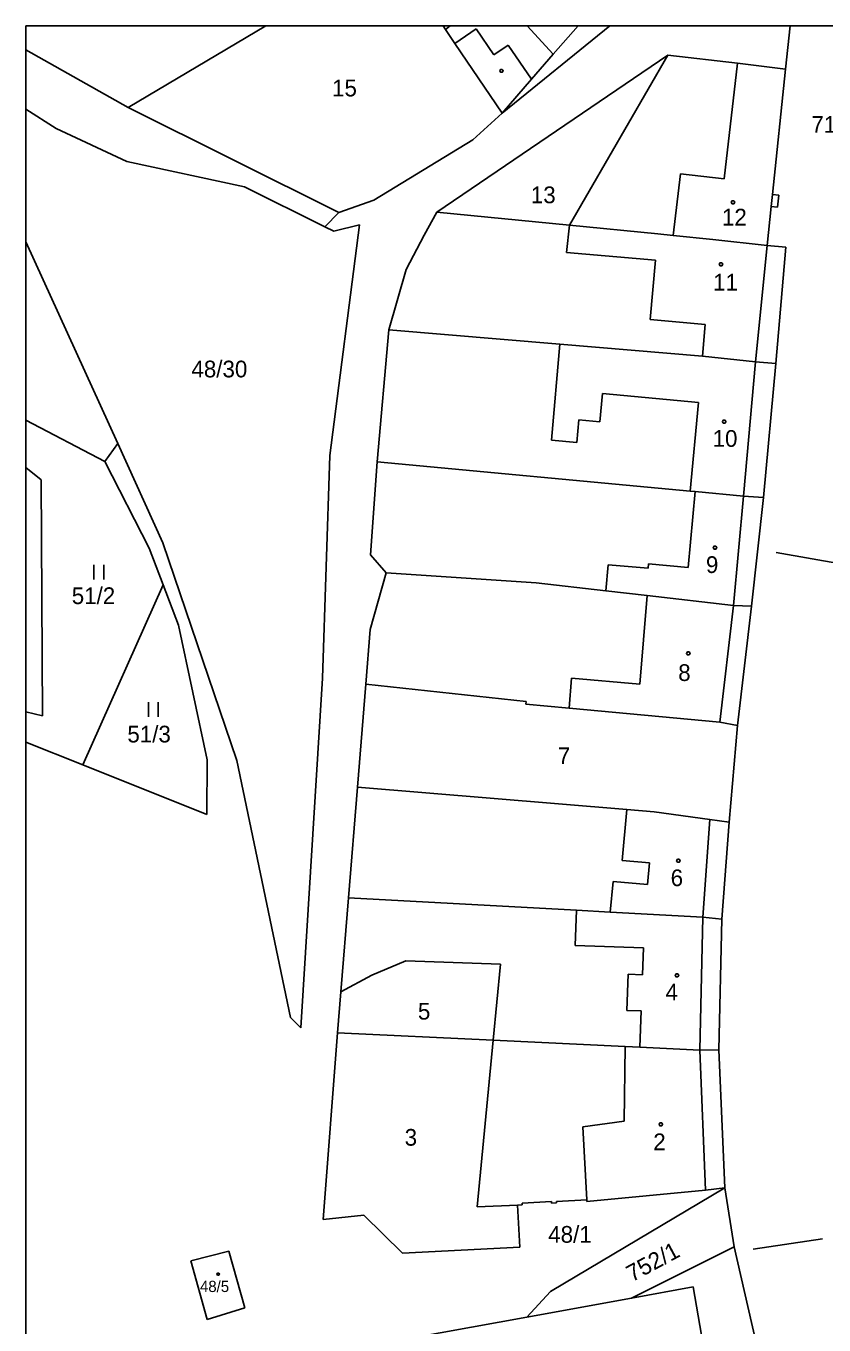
# Model space of a CAD drawing. Extents: x -639590 to -639298, y -1193269 to -1192863.
# Drawn here: x -639590.4 to -639509.2, y -1192995.4 to -1192863.3 of the extents above; entities that cross this region are included whole.
import ezdxf

# ---------------------------------------------------------------- set-up
doc = ezdxf.new("R2010")
doc.units = 0
for name, color, linetype in [('Vrstva 1', 7, 'Continuous'), ('Vrstva 2', 7, 'Continuous'), ('Vrstva 25', 7, 'Continuous'), ('Vrstva 3', 7, 'Continuous'), ('Vrstva 4', 7, 'Continuous'), ('Vrstva 5', 7, 'Continuous'), ('Vrstva 61', 7, 'Continuous')]:
    doc.layers.add(name, color=color, linetype=linetype)

msp = doc.modelspace()

# ---------------------------------------------------------------- linework, layer by layer
at = {"layer": 'Vrstva 1'}
for p, q in [((-639565.97, -1192863.27), (-639580, -1192871.57)), ((-639547.69, -1192863.63), (-639547.93, -1192863.27)), ((-639546.73, -1192865.04), (-639547.69, -1192863.63)), ((-639530.97, -1192863.27), (-639541.93, -1192872.12)), ((-639534.19, -1192863.27), (-639536.75, -1192866.15)), ((-639512.63, -1192863.27), (-639513.1, -1192867.65)), ((-639541.93, -1192872.12), (-639546.73, -1192865.04)), ((-639580, -1192871.57), (-639590.39, -1192865.7)), ((-639525.06, -1192866.23), (-639548.56, -1192882.19)), ((-639536.75, -1192866.15), (-639538.95, -1192868.69)), ((-639525.06, -1192866.23), (-639535.07, -1192883.53)), ((-639517.99, -1192867.05), (-639525.06, -1192866.23)), ((-639513.1, -1192867.65), (-639517.99, -1192867.05)), ((-639514.43, -1192880.41), (-639513.1, -1192867.65)), ((-639538.95, -1192868.69), (-639541.93, -1192872.12)), ((-639590.39, -1192871.73), (-639587.31, -1192873.7)), ((-639580, -1192871.57), (-639558.56, -1192882.23)), ((-639541.93, -1192872.12), (-639544.9, -1192874.86)), ((-639587.31, -1192873.7), (-639580.13, -1192877.06)), ((-639544.9, -1192874.86), (-639555, -1192880.97)), ((-639580.13, -1192877.06), (-639568.16, -1192879.64)), ((-639568.16, -1192879.64), (-639559.97, -1192883.7)), ((-639558.56, -1192882.23), (-639555, -1192880.97)), ((-639513.76, -1192880.48), (-639514.43, -1192880.41)), ((-639513.89, -1192881.71), (-639513.76, -1192880.48)), ((-639559.97, -1192883.7), (-639558.56, -1192882.23)), ((-639548.56, -1192882.19), (-639549.88, -1192884.53)), ((-639535.07, -1192883.53), (-639548.56, -1192882.19)), ((-639514.97, -1192885.59), (-639514.56, -1192881.64)), ((-639514.56, -1192881.64), (-639513.89, -1192881.71)), ((-639559.97, -1192883.7), (-639559.07, -1192884.15)), ((-639556.45, -1192883.48), (-639559.45, -1192906.94)), ((-639559.07, -1192884.15), (-639556.45, -1192883.48)), ((-639526.07, -1192884.42), (-639535.07, -1192883.53)), ((-639581.05, -1192905.73), (-639590.39, -1192885.22)), ((-639551.68, -1192888.03), (-639549.88, -1192884.53)), ((-639524.51, -1192884.57), (-639526.07, -1192884.42)), ((-639520.5, -1192884.97), (-639524.51, -1192884.57)), ((-639514.97, -1192885.59), (-639520.5, -1192884.97)), ((-639513.07, -1192885.76), (-639514.97, -1192885.59)), ((-639514.06, -1192897.59), (-639513.07, -1192885.76)), ((-639553.46, -1192894.18), (-639551.68, -1192888.03)), ((-639553.46, -1192894.18), (-639554.66, -1192907.58)), ((-639536.07, -1192895.63), (-639553.46, -1192894.18)), ((-639521.55, -1192896.85), (-639536.07, -1192895.63)), ((-639516.13, -1192897.41), (-639521.55, -1192896.85)), ((-639514.06, -1192897.59), (-639516.13, -1192897.41)), ((-639515.33, -1192911.2), (-639514.06, -1192897.59)), ((-639590.39, -1192903.36), (-639582.38, -1192907.56)), ((-639581.05, -1192905.73), (-639582.38, -1192907.56)), ((-639576.45, -1192915.83), (-639581.05, -1192905.73)), ((-639582.38, -1192907.56), (-639577.84, -1192916.35)), ((-639559.45, -1192906.94), (-639560.22, -1192929.6)), ((-639555.33, -1192917.06), (-639554.66, -1192907.58)), ((-639522.8, -1192910.56), (-639554.66, -1192907.58)), ((-639590.39, -1192908.18), (-639588.84, -1192909.43)), ((-639588.7, -1192933.43), (-639588.84, -1192909.43)), ((-639522.3, -1192910.61), (-639522.8, -1192910.56)), ((-639517.37, -1192911.07), (-639522.3, -1192910.61)), ((-639515.33, -1192911.2), (-639517.37, -1192911.07)), ((-639516.56, -1192922.27), (-639515.33, -1192911.2)), ((-639568.92, -1192937.95), (-639576.45, -1192915.83)), ((-639577.84, -1192916.35), (-639576.43, -1192920.08)), ((-639553.74, -1192918.86), (-639555.33, -1192917.06)), ((-639553.74, -1192918.86), (-639555.36, -1192924.62)), ((-639538.45, -1192919.9), (-639553.74, -1192918.86)), ((-639576.43, -1192920.08), (-639584.61, -1192938.41)), ((-639576.43, -1192920.08), (-639574.87, -1192924.21)), ((-639531.39, -1192920.71), (-639538.45, -1192919.9)), ((-639527.16, -1192921.19), (-639531.39, -1192920.71)), ((-639518.37, -1192922.19), (-639527.16, -1192921.19)), ((-639516.56, -1192922.27), (-639518.37, -1192922.19)), ((-639517.98, -1192934.38), (-639516.56, -1192922.27)), ((-639574.87, -1192924.21), (-639571.95, -1192937.9)), ((-639555.36, -1192924.62), (-639555.81, -1192930.2)), ((-639560.22, -1192929.6), (-639562.4, -1192965.13)), ((-639556.66, -1192940.65), (-639555.81, -1192930.2)), ((-639539.5, -1192931.94), (-639555.81, -1192930.2)), ((-639590.39, -1192933.02), (-639588.7, -1192933.43)), ((-639539.5, -1192931.94), (-639539.53, -1192932.24)), ((-639535.12, -1192932.64), (-639539.53, -1192932.24)), ((-639519.77, -1192934.05), (-639535.12, -1192932.64)), ((-639517.98, -1192934.38), (-639519.77, -1192934.05)), ((-639518.83, -1192944.22), (-639517.98, -1192934.38)), ((-639590.39, -1192936.1), (-639584.61, -1192938.41)), ((-639571.98, -1192943.45), (-639571.95, -1192937.9)), ((-639563.48, -1192964.08), (-639568.92, -1192937.95)), ((-639584.61, -1192938.41), (-639571.98, -1192943.45)), ((-639557.57, -1192951.91), (-639556.66, -1192940.65)), ((-639529.25, -1192942.94), (-639556.66, -1192940.65)), ((-639526.45, -1192943.17), (-639529.25, -1192942.94)), ((-639520.79, -1192943.95), (-639526.45, -1192943.17)), ((-639518.83, -1192944.22), (-639520.79, -1192943.95)), ((-639519.57, -1192954.08), (-639518.83, -1192944.22)), ((-639558.35, -1192961.49), (-639557.57, -1192951.91)), ((-639534.37, -1192953.17), (-639557.57, -1192951.91)), ((-639530.93, -1192953.36), (-639534.37, -1192953.17)), ((-639521.49, -1192953.87), (-639530.93, -1192953.36)), ((-639519.57, -1192954.08), (-639521.49, -1192953.87)), ((-639519.87, -1192967.38), (-639519.57, -1192954.08)), ((-639555.2, -1192959.79), (-639551.74, -1192958.33)), ((-639542.1, -1192958.67), (-639551.74, -1192958.33)), ((-639542.83, -1192966.4), (-639542.1, -1192958.67)), ((-639558.35, -1192961.49), (-639555.2, -1192959.79)), ((-639558.69, -1192965.64), (-639558.35, -1192961.49)), ((-639562.4, -1192965.13), (-639563.48, -1192964.08)), ((-639558.69, -1192965.64), (-639560.13, -1192984.63)), ((-639542.83, -1192966.4), (-639558.69, -1192965.64)), ((-639542.83, -1192966.4), (-639544.48, -1192983.34)), ((-639529.4, -1192967.04), (-639542.83, -1192966.4)), ((-639527.9, -1192967.11), (-639529.4, -1192967.04)), ((-639521.81, -1192967.4), (-639527.9, -1192967.11)), ((-639519.87, -1192967.38), (-639521.81, -1192967.4)), ((-639519.26, -1192981.41), (-639519.87, -1192967.38)), ((-639519.26, -1192981.41), (-639537.01, -1192991.95)), ((-639521.22, -1192981.65), (-639533.3, -1192982.79)), ((-639521.22, -1192981.65), (-639519.26, -1192981.41)), ((-639519.26, -1192981.41), (-639518.33, -1192987.4)), ((-639544.48, -1192983.34), (-639540.36, -1192983.16)), ((-639540.36, -1192983.16), (-639539.89, -1192983.14)), ((-639540.12, -1192987.45), (-639540.36, -1192983.16)), ((-639539.9, -1192982.97), (-639536.91, -1192982.81)), ((-639539.89, -1192983.14), (-639539.9, -1192982.97)), ((-639536.91, -1192982.81), (-639536.9, -1192982.97)), ((-639536.9, -1192982.97), (-639536.4, -1192982.94)), ((-639533.31, -1192982.61), (-639536.41, -1192982.78)), ((-639536.4, -1192982.94), (-639536.41, -1192982.78)), ((-639533.3, -1192982.79), (-639533.31, -1192982.61)), ((-639560.13, -1192984.63), (-639555.99, -1192984.2)), ((-639555.99, -1192984.2), (-639552.08, -1192988.04)), ((-639573.61, -1192988.84), (-639569.73, -1192987.84)), ((-639569.73, -1192987.84), (-639568.13, -1192993.61)), ((-639540.12, -1192987.45), (-639552.08, -1192988.04)), ((-639518.33, -1192987.4), (-639528.76, -1192992.62)), ((-639518.33, -1192987.4), (-639513.38, -1193008.98)), ((-639571.96, -1192994.78), (-639573.61, -1192988.84)), ((-639537.01, -1192991.95), (-639539.42, -1192994.56)), ((-639528.76, -1192992.62), (-639522.49, -1192991.48)), ((-639521.26, -1192998.64), (-639522.49, -1192991.48)), ((-639568.13, -1192993.61), (-639571.96, -1192994.78)), ((-639539.42, -1192994.56), (-639528.76, -1192992.62)), ((-639553.86, -1192997.18), (-639539.42, -1192994.56))]:
    msp.add_line(p, q, dxfattribs=at)
at = {"layer": 'Vrstva 25'}
for p, q in [((-639514.03, -1192916.81), (-639507.28, -1192917.98)), ((-639516.39, -1192987.64), (-639509.32, -1192986.58))]:
    msp.add_line(p, q, dxfattribs=at)
at = {"layer": 'Vrstva 3'}
for p, q in [((-639583.48, -1192918.05), (-639583.48, -1192919.55)), ((-639582.48, -1192919.55), (-639582.48, -1192918.05)), ((-639577.93, -1192932.02), (-639577.93, -1192933.52)), ((-639576.93, -1192933.52), (-639576.93, -1192932.02))]:
    msp.add_line(p, q, dxfattribs=at)
at = {"layer": 'Vrstva 4'}
for p, q in [((-639547.69, -1192863.63), (-639547.22, -1192863.27)), ((-639544.56, -1192863.57), (-639546.73, -1192865.04)), ((-639542.78, -1192866.2), (-639544.56, -1192863.57)), ((-639536.75, -1192866.15), (-639539.37, -1192863.27)), ((-639541.32, -1192865.21), (-639542.78, -1192866.2)), ((-639538.95, -1192868.69), (-639541.32, -1192865.21)), ((-639517.99, -1192867.05), (-639519.35, -1192878.82)), ((-639524.51, -1192884.57), (-639523.78, -1192878.31)), ((-639523.78, -1192878.31), (-639519.35, -1192878.82)), ((-639514.56, -1192881.64), (-639514.43, -1192880.41)), ((-639535.07, -1192883.53), (-639535.39, -1192886.3)), ((-639535.39, -1192886.3), (-639526.32, -1192887.09)), ((-639514.97, -1192885.59), (-639516.13, -1192897.41)), ((-639526.32, -1192887.09), (-639526.87, -1192893.1)), ((-639526.87, -1192893.1), (-639521.26, -1192893.61)), ((-639521.26, -1192893.61), (-639521.55, -1192896.85)), ((-639536.07, -1192895.63), (-639536.92, -1192905.37)), ((-639516.13, -1192897.41), (-639517.37, -1192911.07)), ((-639531.98, -1192903.52), (-639531.71, -1192900.63)), ((-639531.71, -1192900.63), (-639521.95, -1192901.55)), ((-639521.95, -1192901.55), (-639522.8, -1192910.56)), ((-639534.33, -1192905.61), (-639534.12, -1192903.32)), ((-639534.12, -1192903.32), (-639531.98, -1192903.52)), ((-639536.92, -1192905.37), (-639534.33, -1192905.61)), ((-639522.3, -1192910.61), (-639522.99, -1192918.33)), ((-639517.37, -1192911.07), (-639518.37, -1192922.19)), ((-639531.39, -1192920.71), (-639531.15, -1192918.05)), ((-639531.15, -1192918.05), (-639527.06, -1192918.41)), ((-639527.06, -1192918.41), (-639527.02, -1192917.96)), ((-639527.02, -1192917.96), (-639522.99, -1192918.33)), ((-639527.16, -1192921.19), (-639527.92, -1192930.18)), ((-639518.37, -1192922.19), (-639519.77, -1192934.05)), ((-639535.12, -1192932.64), (-639534.86, -1192929.59)), ((-639534.86, -1192929.59), (-639527.92, -1192930.18)), ((-639529.25, -1192942.94), (-639529.72, -1192948.11)), ((-639520.79, -1192943.95), (-639521.49, -1192953.87)), ((-639529.72, -1192948.11), (-639526.93, -1192948.37)), ((-639527.13, -1192950.57), (-639526.93, -1192948.37)), ((-639530.93, -1192953.36), (-639530.64, -1192950.25)), ((-639530.64, -1192950.25), (-639527.13, -1192950.57)), ((-639534.37, -1192953.17), (-639534.5, -1192956.77)), ((-639521.49, -1192953.87), (-639521.81, -1192967.4)), ((-639527.54, -1192957.02), (-639534.5, -1192956.77)), ((-639527.54, -1192957.02), (-639527.64, -1192959.74)), ((-639529.1, -1192959.69), (-639529.23, -1192963.36)), ((-639527.64, -1192959.74), (-639529.1, -1192959.69)), ((-639529.23, -1192963.36), (-639527.77, -1192963.41)), ((-639527.77, -1192963.41), (-639527.9, -1192967.11)), ((-639529.4, -1192967.04), (-639529.52, -1192974.62)), ((-639521.81, -1192967.4), (-639521.22, -1192981.65)), ((-639529.52, -1192974.62), (-639533.72, -1192975.2)), ((-639533.72, -1192975.2), (-639533.31, -1192982.61))]:
    msp.add_line(p, q, dxfattribs=at)
at = {"layer": 'Vrstva 5'}
for points in [[(-639541.91, -1192867.68), (-639541.82, -1192867.83), (-639541.91, -1192867.98), (-639542.09, -1192867.98), (-639542.18, -1192867.83), (-639542.09, -1192867.68)], [(-639518.35, -1192881.04), (-639518.26, -1192881.19), (-639518.35, -1192881.34), (-639518.53, -1192881.34), (-639518.62, -1192881.19), (-639518.53, -1192881.04)], [(-639519.57, -1192887.35), (-639519.48, -1192887.5), (-639519.57, -1192887.65), (-639519.75, -1192887.65), (-639519.84, -1192887.5), (-639519.75, -1192887.35)], [(-639519.24, -1192903.34), (-639519.15, -1192903.49), (-639519.24, -1192903.64), (-639519.42, -1192903.64), (-639519.51, -1192903.49), (-639519.42, -1192903.34)], [(-639520.18, -1192916.16), (-639520.09, -1192916.31), (-639520.18, -1192916.46), (-639520.36, -1192916.46), (-639520.45, -1192916.31), (-639520.36, -1192916.16)], [(-639522.9, -1192926.92), (-639522.81, -1192927.07), (-639522.9, -1192927.22), (-639523.08, -1192927.22), (-639523.17, -1192927.07), (-639523.08, -1192926.92)], [(-639523.9, -1192948), (-639523.81, -1192948.15), (-639523.9, -1192948.3), (-639524.08, -1192948.3), (-639524.17, -1192948.15), (-639524.08, -1192948)], [(-639524.05, -1192959.66), (-639523.96, -1192959.81), (-639524.05, -1192959.96), (-639524.23, -1192959.96), (-639524.32, -1192959.81), (-639524.23, -1192959.66)], [(-639525.69, -1192974.81), (-639525.6, -1192974.96), (-639525.69, -1192975.11), (-639525.87, -1192975.11), (-639525.96, -1192974.96), (-639525.87, -1192974.81)], [(-639570.77, -1192990.08), (-639570.71, -1192990.18), (-639570.77, -1192990.28), (-639570.89, -1192990.28), (-639570.95, -1192990.18), (-639570.89, -1192990.08)]]:
    msp.add_lwpolyline(points, close=True, dxfattribs=at)
at = {"layer": 'Vrstva 61'}
for points in [[(-639590.39, -1193268.77), (-639590.39, -1192863.27)], [(-639590.39, -1192863.27), (-639298.39, -1192863.27)]]:
    msp.add_lwpolyline(points, dxfattribs=at)

# ---------------------------------------------------------------- texts
at = {"layer": 'Vrstva 2'}
for s, height, p in [('15', 1.7, (-639559.24, -1192870.43)), ('715/1', 1.7, (-639510.46, -1192874.13)), ('13', 1.7, (-639539.01, -1192881.29)), ('12', 1.7, (-639519.56, -1192883.56)), ('11', 1.7, (-639520.46, -1192890.17)), ('48/30', 1.7, (-639573.55, -1192899)), ('10', 1.7, (-639520.51, -1192906.06)), ('9', 1.7, (-639521.19, -1192918.89)), ('51/2', 1.7, (-639585.73, -1192922.05)), ('8', 1.7, (-639524.01, -1192929.87)), ('51/3', 1.7, (-639580.07, -1192936.12)), ('7', 1.7, (-639536.26, -1192938.32)), ('6', 1.7, (-639524.78, -1192950.73)), ('4', 1.7, (-639525.3, -1192962.35)), ('5', 1.7, (-639550.5, -1192964.3)), ('3', 1.7, (-639551.85, -1192977.12)), ('2', 1.7, (-639526.55, -1192977.58)), ('48/1', 1.7, (-639537.24, -1192986.99)), ('48/5', 1.14, (-639572.68, -1192992))]:
    msp.add_text(s, height=height, dxfattribs=at).set_placement(p)
msp.add_text('752/1', height=1.7, rotation=28.2468, dxfattribs=at).set_placement((-639528.71, -1192991.02))

doc.saveas('drawing.dxf')
